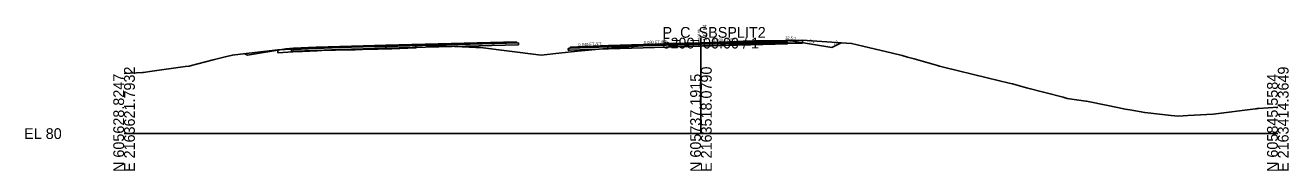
# Model space of a CAD drawing. Extents: x -26 to 1303, y -10 to 12033.
# Drawn here: x -25.7 to 302.8, y 5490.3 to 5528.3 of the extents above; entities that cross this region are included whole.
import ezdxf

# ---------------------------------------------------------------- set-up
doc = ezdxf.new("R2010")
doc.units = 0
for name, color, linetype in [('RD_GPK_XS_Cell', 7, 'Continuous'), ('RD_XS_Base', 7, 'Continuous'), ('RD_XS_ExGround', 7, 'Continuous'), ('RD_XS_ExPaveRet', 7, 'Continuous'), ('RD_XS_Greenside', 7, 'Continuous'), ('RD_XS_Pave', 7, 'Continuous'), ('RD_XS_PaveOvlay_CP', 7, 'Continuous'), ('RD_XS_TieSlope', 7, 'Continuous'), ('RD_XS_TX_Elev_EX', 7, 'Continuous'), ('RD_XS_TX_Elev_PR', 7, 'Continuous'), ('RD_XS_TX_ShdSlope', 7, 'Continuous'), ('RD_XS_TX_Slope', 7, 'Continuous')]:
    doc.layers.add(name, color=color, linetype=linetype)

msp = doc.modelspace()

# ---------------------------------------------------------------- linework, layer by layer
at = {"layer": 'RD_GPK_XS_Cell'}
for p, q in [((150, 5500), (150, 5525)), ((0, 5500), (150, 5500)), ((150, 5500), (300, 5500))]:
    msp.add_line(p, q, dxfattribs=at)
at = {"layer": 'RD_XS_Base'}
for p, q in [((68.08, 5522.75), (62.21, 5522.6)), ((68.08, 5522.75), (102.58, 5523.65)), ((102.58, 5523.15), (68.08, 5522.25)), ((68.08, 5522.25), (68.08, 5522.91)), ((68.08, 5522.91), (68.08, 5522.91)), ((68.08, 5522.91), (68.08, 5522.91)), ((68.08, 5522.91), (68.08, 5522.75)), ((68.08, 5522.75), (68.08, 5522.75)), ((68.08, 5522.25), (68.08, 5522.75)), ((68.08, 5522.75), (68.08, 5522.75)), ((68.08, 5522.75), (68.08, 5522.75)), ((92.08, 5523.38), (92.08, 5523.38)), ((92.08, 5523.38), (92.08, 5523.38)), ((92.08, 5522.88), (92.08, 5522.88)), ((92.08, 5522.88), (92.08, 5522.88)), ((102.08, 5523.64), (102.08, 5523.64)), ((102.58, 5523.65), (102.58, 5523.15)), ((102.58, 5523.62), (102.58, 5523.62)), ((126, 5522.65), (116, 5522.25)), ((150, 5523.32), (126, 5522.65)), ((126, 5522.15), (150, 5522.82)), ((126, 5522.65), (126, 5522.65)), ((150, 5523.32), (172, 5523.94)), ((150, 5522.82), (150, 5523.48)), ((150, 5523.48), (150, 5523.48)), ((150, 5523.48), (150, 5523.48)), ((150, 5523.48), (150, 5523.32)), ((172.5, 5523.45), (150, 5522.82)), ((150, 5523.32), (150, 5523.32)), ((150, 5522.82), (150, 5523.32)), ((150, 5523.32), (150, 5523.32)), ((150, 5523.32), (150, 5523.32)), ((150, 5522.82), (150, 5522.82)), ((162, 5523.66), (162, 5523.66)), ((162, 5523.66), (162, 5523.66)), ((162, 5523.16), (162, 5523.16)), ((162, 5523.16), (162, 5523.16)), ((172, 5523.94), (172, 5523.94)), ((172.5, 5523.95), (172.5, 5523.45)), ((172.5, 5523.92), (172.5, 5523.92)), ((43.82, 5521.95), (43.57, 5521.94)), ((43.57, 5521.94), (43.57, 5521.69)), ((43.57, 5521.69), (43.57, 5521.44)), ((43.57, 5521.44), (43.82, 5521.45)), ((44.07, 5521.96), (43.82, 5521.95)), ((43.82, 5521.45), (44.07, 5521.46)), ((49.99, 5522.2), (44.07, 5521.96)), ((44.07, 5521.46), (49.99, 5521.7)), ((56.07, 5522.44), (49.99, 5522.2)), ((49.99, 5521.7), (56.07, 5521.94)), ((62.21, 5522.6), (56.07, 5522.44)), ((56.07, 5521.94), (62.21, 5522.1)), ((62.21, 5522.1), (68.08, 5522.25)), ((68.08, 5522.25), (68.08, 5522.25)), ((116, 5522.25), (115.5, 5522.23)), ((115.5, 5522.23), (115.5, 5522.23)), ((115.5, 5522.23), (115.5, 5521.73)), ((115.5, 5521.73), (116, 5521.75)), ((116, 5522.25), (116, 5522.25)), ((116, 5521.75), (126, 5522.15)), ((116, 5521.75), (116, 5521.75)), ((126, 5522.15), (126, 5522.15))]:
    msp.add_line(p, q, dxfattribs=at)
at = {"layer": 'RD_XS_ExGround'}
msp.add_lwpolyline([(0, 5515.71), (4.75, 5515.91), (5.03, 5515.92), (5.57, 5516), (6.69, 5516.17), (15.92, 5517.51), (16.91, 5517.59), (17.19, 5517.68), (23.13, 5519.2), (26.32, 5520.01), (28.15, 5520.5), (28.78, 5520.56), (40.02, 5521.83), (46.37, 5522.17), (50.96, 5522.41), (53.57, 5522.49), (54.77, 5522.5), (54.97, 5522.52), (58.62, 5522.57), (59.68, 5522.61), (60.13, 5522.64), (60.56, 5522.65), (61.8, 5522.67), (65.83, 5522.79), (75.89, 5523.08), (83.88, 5522.81), (87.87, 5522.65), (91.43, 5522.5), (92.7, 5522.47), (99.54, 5521.59), (108.48, 5520.5), (113.03, 5520.96), (117.91, 5521.5), (124.46, 5522.08), (128.98, 5522.49), (131.28, 5522.59), (137.11, 5523.04), (141.76, 5523.47), (150.43, 5523.68), (152.94, 5523.77), (157.29, 5523.94), (160.94, 5524.08), (163.74, 5524.22), (171.88, 5524.31), (176.38, 5524.34), (180.16, 5524.08), (189.15, 5523.51), (192.13, 5522.84), (199.85, 5520.96), (202.32, 5520.37), (203.71, 5519.93), (205.47, 5519.5), (211.49, 5517.75), (212.06, 5517.62), (213.05, 5517.34), (224.46, 5514.55), (230.12, 5513.17), (231, 5512.97), (234.61, 5511.98), (244.17, 5509.5), (245.22, 5509.2), (250.1, 5508.48), (250.27, 5508.46), (251.13, 5508.28), (258.75, 5506.69), (259.91, 5506.5), (260.31, 5506.4), (261.51, 5506.21), (265.42, 5505.5), (272.27, 5504.76), (274.14, 5504.58), (276.63, 5504.7), (283.22, 5505.1), (294.22, 5506.47), (294.45, 5506.49), (294.55, 5506.51), (294.95, 5506.54), (300, 5506.86)], dxfattribs=at)
at = {"layer": 'RD_XS_ExPaveRet'}
for points in [[(66.01, 5522.79), (61.9, 5522.67), (60.64, 5522.65), (60.55, 5522.65), (60.42, 5522.65), (60.13, 5522.64), (60.05, 5522.64), (59.68, 5522.61), (59.49, 5522.6), (58.62, 5522.57), (57.94, 5522.56), (54.97, 5522.52), (54.8, 5522.5), (54.77, 5522.5), (54.61, 5522.5), (53.57, 5522.49), (51.39, 5522.42), (50.96, 5522.41), (50.19, 5522.37), (46.37, 5522.17), (43.85, 5522.04), (40.02, 5521.83), (40.02, 5521.58), (40.02, 5521.08), (43.85, 5521.29), (46.37, 5521.42), (50.19, 5521.62), (50.96, 5521.66), (51.39, 5521.67), (53.57, 5521.74), (54.61, 5521.75), (54.77, 5521.75), (54.8, 5521.75), (54.97, 5521.77), (57.94, 5521.81), (58.62, 5521.82), (59.49, 5521.85), (59.68, 5521.86), (60.05, 5521.89), (60.13, 5521.89), (60.42, 5521.9), (60.55, 5521.9), (60.64, 5521.9), (61.9, 5521.92), (66.01, 5522.04), (69.58, 5522.15), (75.89, 5522.33), (75.89, 5522.92), (75.89, 5523.08), (69.58, 5522.9), (66.01, 5522.79)], [(66.01, 5522.79), (61.9, 5522.67), (60.64, 5522.65), (60.55, 5522.65), (60.42, 5522.65), (60.13, 5522.64), (60.05, 5522.64), (59.68, 5522.61), (59.49, 5522.6), (58.62, 5522.57), (57.94, 5522.56), (54.97, 5522.52), (54.8, 5522.5), (54.77, 5522.5), (54.61, 5522.5), (53.57, 5522.49), (51.39, 5522.42), (50.96, 5522.41), (50.19, 5522.37), (46.37, 5522.17), (43.85, 5522.04), (40.02, 5521.83), (40.02, 5521.58), (40.02, 5521.08), (43.85, 5521.29), (46.37, 5521.42), (50.19, 5521.62), (50.96, 5521.66), (51.39, 5521.67), (53.57, 5521.74), (54.61, 5521.75), (54.77, 5521.75), (54.8, 5521.75), (54.97, 5521.77), (57.94, 5521.81), (58.62, 5521.82), (59.49, 5521.85), (59.68, 5521.86), (60.05, 5521.89), (60.13, 5521.89), (60.42, 5521.9), (60.55, 5521.9), (60.64, 5521.9), (61.9, 5521.92), (66.01, 5522.04), (69.58, 5522.15), (75.89, 5522.33), (75.89, 5522.92), (75.89, 5523.08), (69.58, 5522.9), (66.01, 5522.79)], [(176.38, 5524.34), (176.38, 5524.34), (171.88, 5524.31), (171.88, 5524.31), (163.74, 5524.22), (163.74, 5524.22), (160.94, 5524.08), (160.94, 5524.08), (157.29, 5523.94), (157.29, 5523.94), (152.94, 5523.77), (150.43, 5523.68), (150.43, 5523.68), (141.76, 5523.47), (141.76, 5523.47), (141.76, 5523.47), (141.76, 5522.72), (141.76, 5522.72), (150.43, 5522.93), (150.43, 5522.93), (152.94, 5523.02), (157.29, 5523.19), (157.29, 5523.19), (160.94, 5523.33), (160.94, 5523.33), (163.74, 5523.47), (163.74, 5523.47), (171.88, 5523.56), (171.88, 5523.56), (176.38, 5523.59), (176.38, 5523.59), (176.38, 5523.59), (176.38, 5524.34), (176.38, 5524.34), (176.38, 5524.34)], [(176.38, 5524.34), (171.88, 5524.31), (163.74, 5524.22), (160.94, 5524.08), (157.29, 5523.94), (152.94, 5523.77), (150.43, 5523.68), (141.76, 5523.47), (141.76, 5522.72), (150.43, 5522.93), (152.94, 5523.02), (157.29, 5523.19), (160.94, 5523.33), (163.74, 5523.47), (171.88, 5523.56), (176.38, 5523.59), (176.38, 5523.59), (176.38, 5524.34), (176.38, 5524.34)]]:
    msp.add_lwpolyline(points, dxfattribs=at)
at = {"layer": 'RD_XS_Greenside'}
for p, q in [((174, 5524.1), (184, 5522.43)), ((184, 5522.43), (186.5, 5523.68)), ((32.07, 5520.46), (31.26, 5520.86)), ((42.07, 5522.12), (32.07, 5520.46))]:
    msp.add_line(p, q, dxfattribs=at)
at = {"layer": 'RD_XS_Pave'}
for p, q in [((56.07, 5522.76), (49.99, 5522.52)), ((62.21, 5522.92), (56.07, 5522.76)), ((56.07, 5522.6), (62.21, 5522.76)), ((62.21, 5522.76), (56.07, 5522.6)), ((68.08, 5523.07), (62.21, 5522.92)), ((62.21, 5522.76), (68.08, 5522.91)), ((68.08, 5522.91), (62.21, 5522.76)), ((62.21, 5522.6), (68.08, 5522.75)), ((102.08, 5523.96), (68.08, 5523.07)), ((102.08, 5523.8), (68.08, 5522.91)), ((68.08, 5522.91), (102.08, 5523.8)), ((68.08, 5522.75), (102.08, 5523.64)), ((68.08, 5523.07), (68.08, 5523.07)), ((68.08, 5522.91), (68.08, 5522.91)), ((68.08, 5522.91), (68.08, 5522.91)), ((68.08, 5522.91), (68.08, 5522.75)), ((68.08, 5522.91), (68.08, 5522.91)), ((68.08, 5522.75), (68.08, 5522.91)), ((68.08, 5522.91), (68.08, 5522.91)), ((68.08, 5522.91), (68.08, 5522.91)), ((68.08, 5522.75), (68.08, 5522.75)), ((68.08, 5522.75), (68.08, 5522.75)), ((92.08, 5523.7), (92.08, 5523.7)), ((92.08, 5523.7), (92.08, 5523.7)), ((92.08, 5523.54), (92.08, 5523.54)), ((92.08, 5523.54), (92.08, 5523.54)), ((92.08, 5523.54), (92.08, 5523.54)), ((92.08, 5523.54), (92.08, 5523.54)), ((92.08, 5523.38), (92.08, 5523.38)), ((92.08, 5523.38), (92.08, 5523.38)), ((102.08, 5523.8), (102.08, 5523.96)), ((102.08, 5523.96), (102.08, 5523.96)), ((102.08, 5523.64), (102.08, 5523.8)), ((102.08, 5523.8), (102.08, 5523.8)), ((126, 5522.97), (116, 5522.57)), ((116, 5522.41), (126, 5522.81)), ((126, 5522.81), (116, 5522.41)), ((116, 5522.25), (126, 5522.65)), ((150, 5523.64), (126, 5522.97)), ((126, 5522.81), (150, 5523.48)), ((150, 5523.48), (126, 5522.81)), ((126, 5522.65), (150, 5523.32)), ((126, 5522.97), (126, 5522.97)), ((126, 5522.81), (126, 5522.81)), ((126, 5522.81), (126, 5522.81)), ((126, 5522.65), (126, 5522.65)), ((172, 5524.26), (150, 5523.64)), ((172, 5524.1), (150, 5523.48)), ((150, 5523.48), (172, 5524.1)), ((150, 5523.32), (172.5, 5523.95)), ((150, 5523.64), (150, 5523.64)), ((150, 5523.48), (150, 5523.48)), ((150, 5523.48), (150, 5523.48)), ((150, 5523.48), (150, 5523.32)), ((150, 5523.48), (150, 5523.48)), ((150, 5523.32), (150, 5523.48)), ((150, 5523.48), (150, 5523.48)), ((150, 5523.48), (150, 5523.48)), ((150, 5523.32), (150, 5523.32)), ((150, 5523.32), (150, 5523.32)), ((162, 5523.98), (162, 5523.98)), ((162, 5523.98), (162, 5523.98)), ((162, 5523.82), (162, 5523.82)), ((162, 5523.82), (162, 5523.82)), ((162, 5523.82), (162, 5523.82)), ((162, 5523.82), (162, 5523.82)), ((162, 5523.66), (162, 5523.66)), ((162, 5523.66), (162, 5523.66)), ((172, 5524.1), (172, 5524.26)), ((172, 5524.26), (172, 5524.26)), ((172, 5523.94), (172, 5524.1)), ((172, 5524.1), (172, 5524.1)), ((49.99, 5522.52), (44.07, 5522.28)), ((44.07, 5522.12), (49.99, 5522.36)), ((49.99, 5522.36), (44.07, 5522.12)), ((44.07, 5522.28), (44.07, 5522.2)), ((44.07, 5522.2), (44.07, 5522.12)), ((44.07, 5521.96), (49.99, 5522.2)), ((44.07, 5522.12), (44.07, 5522.04)), ((44.07, 5522.04), (44.07, 5521.96)), ((49.99, 5522.36), (56.07, 5522.6)), ((56.07, 5522.6), (49.99, 5522.36)), ((49.99, 5522.2), (56.07, 5522.44)), ((56.07, 5522.44), (62.21, 5522.6)), ((116, 5522.57), (116, 5522.57)), ((116, 5522.57), (116, 5522.41)), ((116, 5522.41), (116, 5522.41)), ((116, 5522.41), (116, 5522.25))]:
    msp.add_line(p, q, dxfattribs=at)
at = {"layer": 'RD_XS_PaveOvlay_CP'}
for p, q in [((56.07, 5522.76), (49.99, 5522.52)), ((62.21, 5522.92), (56.07, 5522.76)), ((68.08, 5523.07), (62.21, 5522.92)), ((102.08, 5523.96), (68.08, 5523.07)), ((68.08, 5523.07), (68.08, 5523.07)), ((92.08, 5523.7), (92.08, 5523.7)), ((92.08, 5523.7), (92.08, 5523.7)), ((126, 5522.97), (116, 5522.57)), ((150, 5523.64), (126, 5522.97)), ((126, 5522.97), (126, 5522.97)), ((172, 5524.26), (150, 5523.64)), ((150, 5523.64), (150, 5523.64)), ((162, 5523.98), (162, 5523.98)), ((162, 5523.98), (162, 5523.98)), ((49.99, 5522.52), (44.07, 5522.28))]:
    msp.add_line(p, q, dxfattribs=at)
at = {"layer": 'RD_XS_TieSlope'}
for p, q in [((172, 5524.26), (174, 5524.1)), ((44.07, 5522.28), (42.07, 5522.12))]:
    msp.add_line(p, q, dxfattribs=at)

# ---------------------------------------------------------------- texts
at = {"layer": 'RD_GPK_XS_Cell'}
for s, p in [('P_C_SBSPLIT2', (140, 5525)), ('5290+00.00 / 1', (140, 5522.2)), ('EL 80', (-26, 5498.6))]:
    msp.add_text(s, height=2.8, dxfattribs=at).set_placement(p)
for s, p in [('E 2163621.7932', (2.8, 5490)), ('E 2163518.0790', (152.8, 5490)), ('E 2163414.3649', (302.8, 5490)), ('N 605628.8247', (0, 5490)), ('N 605737.1915', (150, 5490)), ('N 605845.5584', (300, 5490))]:
    msp.add_text(s, height=2.8, rotation=90, dxfattribs=at).set_placement(p)
at = {"layer": 'RD_XS_TX_Elev_EX'}
msp.add_text('103.68', height=0.6, rotation=90, dxfattribs=at).set_placement((149.78, 5524.64))
at = {"layer": 'RD_XS_TX_Elev_PR'}
msp.add_text('103.64', height=1, rotation=90, dxfattribs=at).set_placement((151.47, 5524.22))
at = {"layer": 'RD_XS_TX_ShdSlope'}
msp.add_text('12.5:1', height=0.75, rotation=355.4261, dxfattribs=at).set_placement((171.84, 5524.65))
at = {"layer": 'RD_XS_TX_Slope'}
for s, rotation, p in [('0.040 FT./FT.', 2.2906, (118.15, 5522.81)), ('0.030 FT./FT.', 1.7184, (135.16, 5523.4)), ('0.030 FT./FT.', 1.7184, (153.16, 5523.94)), ('6:1', 350.5358, (178.13, 5523.82)), ('2:1', 26.5651, (184.57, 5523.16))]:
    msp.add_text(s, height=0.75, rotation=rotation, dxfattribs=at).set_placement(p)

doc.saveas('drawing.dxf')
